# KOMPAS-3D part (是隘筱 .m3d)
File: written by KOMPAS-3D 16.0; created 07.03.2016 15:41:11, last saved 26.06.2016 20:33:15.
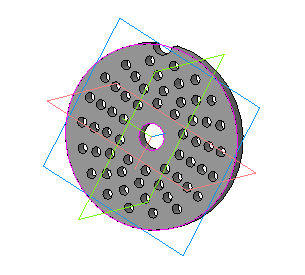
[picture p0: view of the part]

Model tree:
1. Эскиз:1
2. Операция выдавливания:1
     Расстояние 1 = 4
3. Эскиз:2
4. Вырезать элемент выдавливания:1
     Расстояние 1 = 10
5. Массив по концентрической сетке:2  (with: Эскиз:2, Вырезать элемент выдавливания:1)  (labels: v611_1_2_v27; v611_1_2_v180; v611_1_2_v181; Толщина стенки 1)  (10 pattern instances)
     Шаг 2 = 360
6. Эскиз:3
7. Вырезать элемент выдавливания:2  (with: Массив по концентрической сетке:2, Эскиз:3)  (14 pattern instances)
     Расстояние 1 = 10; Геометрический массив = 13; N 1 = 1; Шаг 1 = 10; Шаг 2 = 360; Номер 1 = 1
8. Эскиз:4
9. Вырезать элемент выдавливания:3
     Расстояние 1 = 10
10. Массив по концентрической сетке:3  (with: Вырезать элемент выдавливания:3, Эскиз:4)  (16 pattern instances)
     Геометрический массив = 15; Шаг 2 = 360
11. Эскиз:5
12. Вырезать элемент выдавливания:4
     Расстояние 1 = 10
13. Массив по концентрической сетке:4  (with: Вырезать элемент выдавливания:4, Эскиз:5)  (18 pattern instances)
     Геометрический массив = 17; Шаг 2 = 360
14. Эскиз:6
15. Вырезать элемент выдавливания:6
     Расстояние 1 = 10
